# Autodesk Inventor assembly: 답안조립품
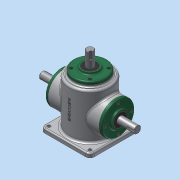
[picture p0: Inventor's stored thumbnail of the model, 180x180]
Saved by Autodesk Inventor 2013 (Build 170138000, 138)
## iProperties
Created: 2015-10
Part Number: 답안조립품
Document SubType Name: Assembly
Designer: Administrator
Author: Administrator
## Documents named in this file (10)
- C:\Users\Administrator\Desktop\451008V1008\답안조립품.iam
- C:\Users\Administrator\Desktop\451008V1008\1-본체.ipt
- C:\Users\Administrator\Desktop\451008V1008\커버.ipt
- C:\Users\Administrator\Desktop\451008V1008\베어링 6203.ipt
- C:\Users\Administrator\Desktop\451008V1008\오일실.ipt
- C:\Users\Administrator\Desktop\451008V1008\메인 축.ipt
- 메인 축.ipt
- C:\Users\Administrator\Desktop\451008V1008\M4.ipt
- C:\Users\Administrator\Desktop\451008V1008\서브 축.ipt
- 서브 축.ipt
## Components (13 placed, 2 different names)
1. 1-본체:1
2. M4:1
3. M4:4
4. M4:5
5. M4:6
6. M4:3
7. M4:7
8. M4:8
9. M4:9
10. M4:2
11. M4:10
12. M4:11
13. M4:12
